// Mitsubishi GX Works2 project: FX3U   PLC: FX3U/FX3UC

PROGRAM MAIN
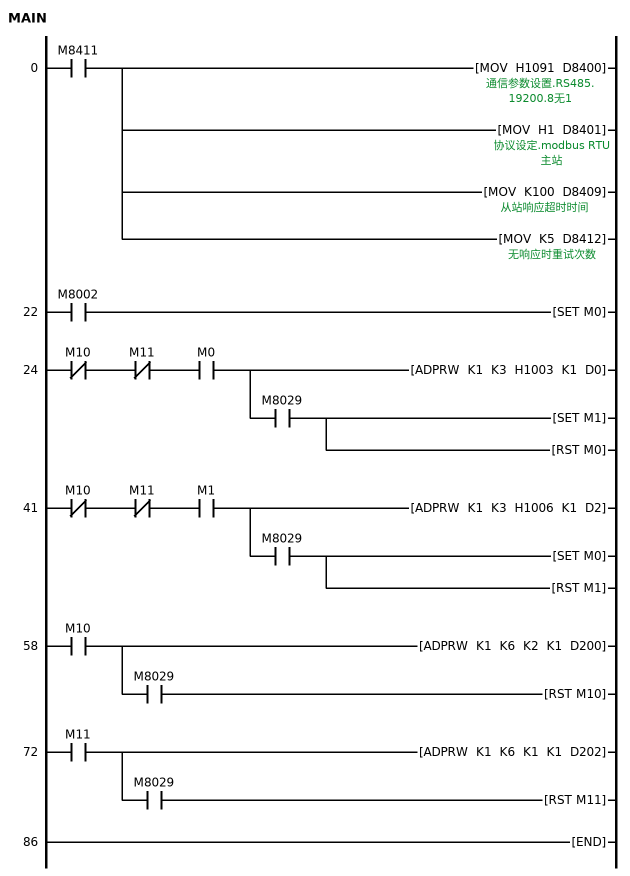
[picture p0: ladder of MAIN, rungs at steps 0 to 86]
0     LD      M8411
      MOV     H1091 D8400  ; 通信参数设置.RS485.19200.8无1
      MOV     H1 D8401  ; 协议设定.modbus RTU 主站
      MOV     K100 D8409  ; 从站响应超时时间
      MOV     K5 D8412  ; 无响应时重试次数
22    LD      M8002
      SET     M0
24    LDI     M10
      ANI     M11
      AND     M0
      ADPRW   K1 K3 H1003 K1 D0
      AND     M8029
      SET     M1
      RST     M0
41    LDI     M10
      ANI     M11
      AND     M1
      ADPRW   K1 K3 H1006 K1 D2
      AND     M8029
      SET     M0
      RST     M1
58    LD      M10
      ADPRW   K1 K6 K2 K1 D200
      AND     M8029
      RST     M10
72    LD      M11
      ADPRW   K1 K6 K1 K1 D202
      AND     M8029
      RST     M11
86    END
END_PROGRAM
